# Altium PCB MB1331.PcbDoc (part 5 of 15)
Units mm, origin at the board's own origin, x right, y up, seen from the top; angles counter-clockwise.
Board outline 169.25 x 173.25 mm, 6 copper layers (Top Layer, Signal Layer 1, Signal Layer 2, Signal Layer 3, Signal Layer 4, Bottom Layer), stack 1.556 mm thick; 871 components, 699 nets, 3244 pads, 2370 vias.
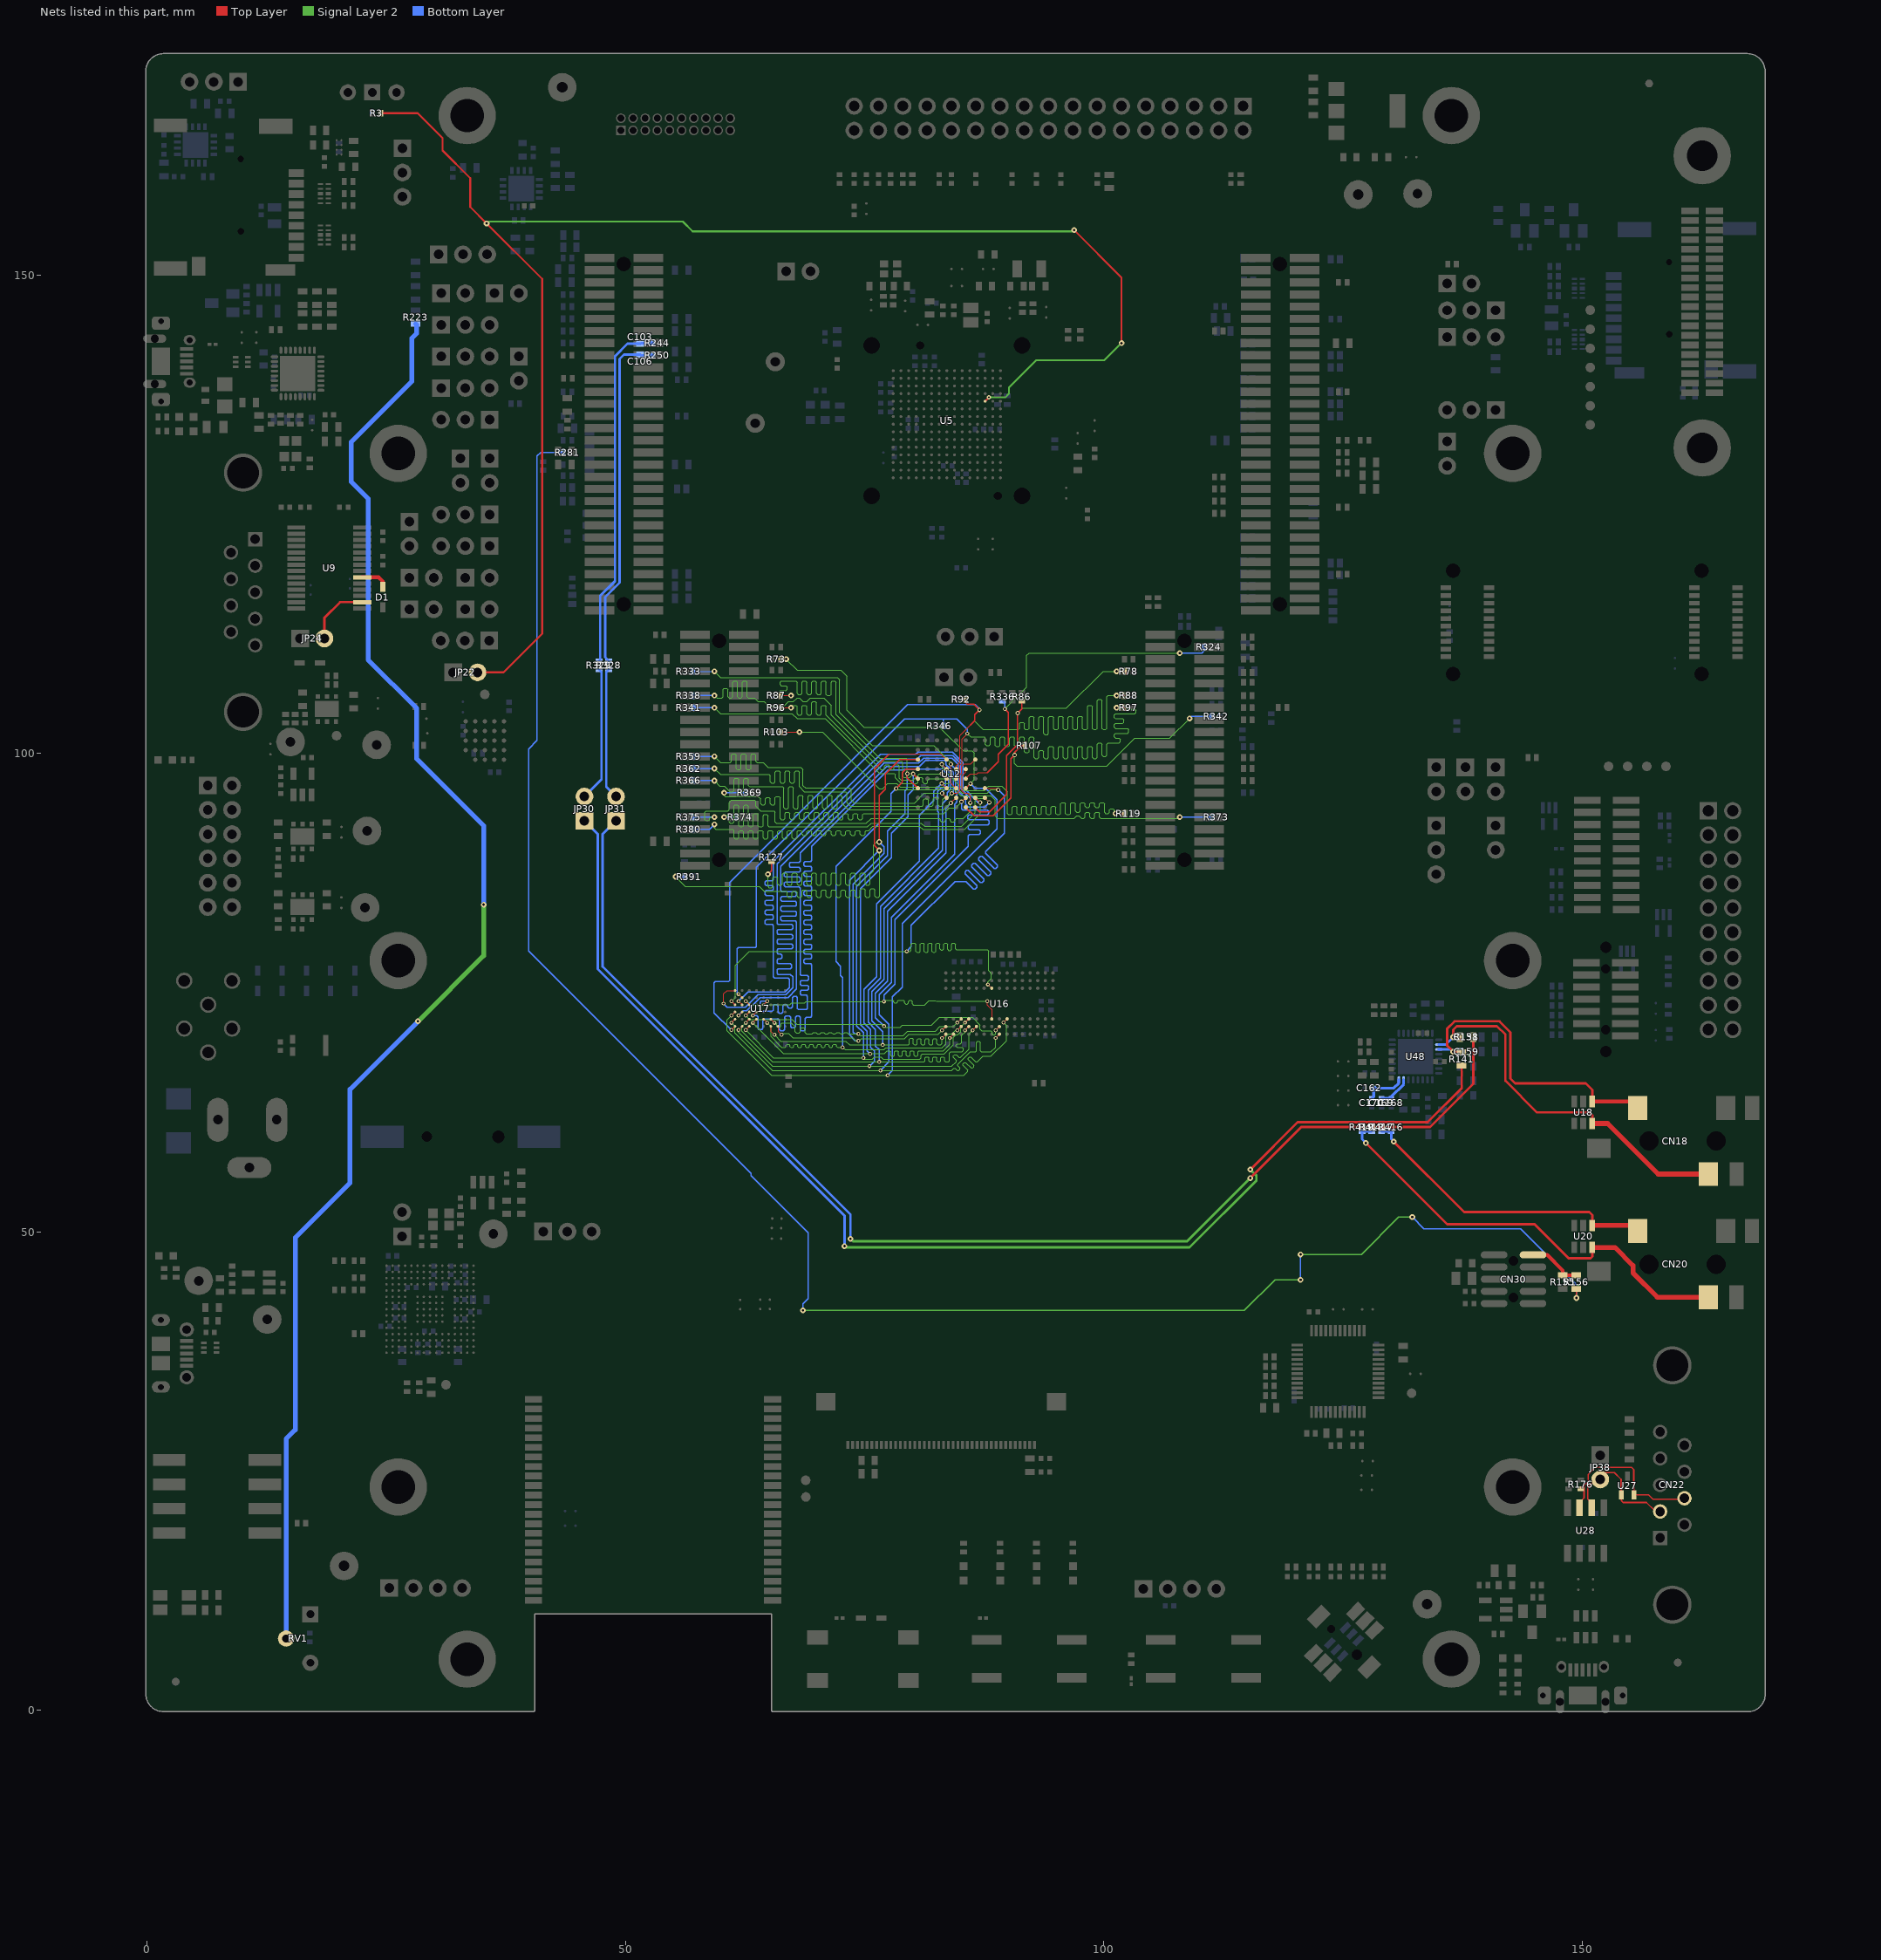
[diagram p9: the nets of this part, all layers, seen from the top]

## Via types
v1: diameter 0.6, hole 0.254, Top Layer to Bottom Layer, tented both sides, 1747 vias
v2: diameter 0.45, hole 0.2, Top Layer to Bottom Layer, tented both sides, 272 vias
v3: diameter 0.406, hole 0.203, Top Layer to Bottom Layer, tented both sides, 160 vias
v4: diameter 0.6, hole 0.25, Top Layer to Bottom Layer, tented both sides, 82 vias
v5: diameter 0.45, hole 0.25, Top Layer to Bottom Layer, tented both sides, 45 vias
v6: diameter 0.5, hole 0.25, Top Layer to Bottom Layer, tented both sides, 23 vias
v7: diameter 1.016, hole 0.508, Top Layer to Bottom Layer, tented both sides, 17 vias
v8: diameter 0.508, hole 0.254, Top Layer to Bottom Layer, tented both sides, 9 vias
v9: diameter 0.61, hole 0.305, Top Layer to Bottom Layer, tented both sides, 7 vias
v10: diameter 0.5, hole 0.254, Top Layer to Bottom Layer, tented both sides, 6 vias
v11: diameter 0.4, hole 0.2, Top Layer to Bottom Layer, tented both sides, 1 vias
v12: diameter 0.483, hole 0.254, Top Layer to Bottom Layer, tented both sides, 1 vias

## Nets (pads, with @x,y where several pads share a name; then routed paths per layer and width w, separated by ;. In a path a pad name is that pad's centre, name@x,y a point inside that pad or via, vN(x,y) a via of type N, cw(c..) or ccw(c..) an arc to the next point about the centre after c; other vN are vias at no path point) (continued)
A9: R103.2 U12.A6 U16.J3 U17.H3 | length 108.3
  Top Layer w0.102: v3(61.078,74.105) U17.H3@61.453,73.73 ; R103.2@66.236,102.235 v1(68.199,102.235) ; U12.A6@87.574,96.366 88.806,96.366 v5(88.97,96.203) ; v3(87.896,75.863) U16.J3@88.297,75.463
  Signal Layer 2 w0.102: v3(61.078,74.105) 61.472,74.5 61.472,77.862 62.935,79.324 v3(79.406,79.324) 79.749,79.324 79.876,79.451 79.876,80.061 80.003,80.188 80.232,80.188 80.359,80.061 80.359,79.324 80.486,79.197 80.71,79.197 80.837,79.324 80.837,80.069 80.956,80.188 81.124,80.188 81.243,80.069 81.243,79.316 81.362,79.197 81.53,79.197 81.65,79.316 81.65,80.069 81.769,80.188 81.937,80.188 82.056,80.069 82.056,79.316 82.175,79.197 82.343,79.197 82.462,79.316 82.462,80.069 82.581,80.188 82.75,80.188 82.869,80.069 82.869,79.57 82.988,79.451 83.156,79.451 83.275,79.57 83.275,80.069 83.394,80.188 83.562,80.188 83.682,80.069 83.682,79.52 83.801,79.401 83.969,79.401 84.088,79.52 84.088,80.061 84.19,80.163 84.393,80.163 84.494,80.061 84.494,79.604 84.596,79.502 87.827,79.502 87.954,79.375 87.954,77.292 88.258,76.988 88.258,76.48 87.896,76.118 v3(87.896,75.863) ; v1(68.199,102.235) 70.612,102.235 76.53,96.317 76.886,96.317 77.419,96.85 78.357,96.85 78.735,96.472 84.566,96.472 85.204,95.834 87.833,95.834 88.202,96.202 v5(88.97,96.203)
  Bottom Layer w0.127: v3(79.406,79.324) 79.876,79.801 79.876,82.037 84.454,86.614 85.58,86.614 86.385,85.809 86.564,85.809 86.745,85.989 86.745,86.169 85.489,87.425 85.489,87.604 85.669,87.784 85.848,87.784 87.104,86.528 87.283,86.528 87.463,86.708 87.463,86.887 86.195,88.156 86.195,88.335 86.375,88.516 86.555,88.516 87.823,87.247 88.002,87.247 88.182,87.427 88.182,87.606 86.914,88.875 86.914,89.054 87.094,89.234 87.273,89.234 88.542,87.966 88.721,87.966 88.905,88.15 88.905,88.33 87.675,89.559 87.675,89.739 89.605,91.669 89.605,95.568 v5(88.97,96.203)
A10: R73.1 U12.C6 U16.G7 U17.H4 | length 108.3
  Top Layer w0.102: v3(61.078,72.605) U17.H4@61.453,72.98 ; R73.1@66.236,109.855 v1(66.802,109.855) ; U12.C6@85.574,96.366 85.583,96.366 v5(86.067,96.85) ; v3(89.52,71.886) U16.G7@89.897,72.263
  Signal Layer 2 w0.102: v3(61.078,72.605) 60.649,72.176 60.649,70.993 65.271,66.37 v3(77.413,66.37) 85.374,66.37 85.795,66.791 85.795,66.891 85.263,67.422 85.263,67.566 85.407,67.71 85.551,67.71 86.131,67.129 86.299,67.129 86.419,67.249 86.419,67.417 85.838,67.997 85.838,68.141 85.982,68.285 86.126,68.285 86.618,67.793 86.785,67.793 87.357,68.364 88.22,68.364 89.833,69.977 89.833,71.572 v3(89.52,71.886) ; v1(66.802,109.855) 67.945,108.712 72.517,108.712 73.152,108.077 73.152,104.521 74.931,102.742 82.831,102.742 83.325,102.248 83.325,102.242 85.307,100.26 86.237,100.26 86.468,100.029 86.468,97.251 v5(86.067,96.85)
  Bottom Layer w0.127: v3(77.413,66.37) 77.921,66.878 77.921,74.565 78.949,75.594 78.949,82.233 88.843,92.126 88.843,95.149 87.649,96.342 86.575,96.342 v5(86.067,96.85)
A11: R333.1 U12.D6 U16.H9 U17.H5 | length 108.2
  Top Layer w0.102: v3(61.078,71.855) U17.H5@61.453,72.23 ; v5(84.017,98.882) 84.017,96.917 U12.D6@84.574,96.366 ; v3(88.697,70.263) U16.H9@89.097,70.663
  Signal Layer 2 w0.102: v1(59.309,108.585) 59.944,107.95 72.136,107.95 72.39,107.696 72.39,104.267 75.819,100.838 82.245,100.838 84.023,99.06 v5(84.017,98.882) ; v3(61.078,71.855) 61.433,71.5 61.433,70.793 65.348,66.878 v3(76.651,66.878) 84.118,66.878 84.315,67.075 84.459,67.075 84.684,66.851 84.827,66.851 84.971,66.995 84.971,67.138 84.747,67.363 84.747,67.507 86.061,68.821 86.582,68.821 86.684,68.923 86.684,69.807 86.803,69.926 86.971,69.926 87.09,69.807 87.09,68.923 87.192,68.821 88.22,68.821 88.697,69.298 v3(88.697,70.263)
  Bottom Layer w0.102: R333.1@57.088,108.585 v1(59.309,108.585)
  Bottom Layer w0.127: v3(76.651,66.878) 77.54,67.767 77.54,71.677 76.524,72.693 76.524,74.785 77.794,76.055 77.794,82.88 84.398,89.484 84.398,94.674 84.652,94.928 84.652,95.834 84.525,95.961 84.525,98.374 v5(84.017,98.882)
A12: R380.1 U12.B7 U17.G3 | length 107.6
  Top Layer w0.102: v3(61.828,74.105) U17.G3@62.203,73.73 ; v5(87.067,94.866) U12.B7@86.602,95.331 ; U12.B7@86.602,95.331 86.599,95.335 U12.B7@86.574,95.366 U12.B7@86.602,95.331
  Signal Layer 2 w0.1: 59.944,92.075 61.214,92.075 61.341,91.948 61.341,91.186 61.468,91.059 61.722,91.059 61.849,91.186 61.849,91.821 61.976,91.948 62.23,91.948 62.357,91.821 62.357,91.186 62.484,91.059 62.738,91.059 62.865,91.186 62.865,91.821 62.992,91.948 63.246,91.948 63.373,91.821 63.373,91.186 63.5,91.059 63.754,91.059 63.881,91.186 63.881,91.821 64.008,91.948 64.262,91.948 64.389,91.821 64.389,91.186 64.516,91.059 64.77,91.059 64.897,91.186 64.897,91.821 65.024,91.948 65.278,91.948 65.405,91.821 65.405,91.186 65.532,91.059 65.786,91.059 65.913,91.186 65.913,91.821 66.04,91.948 66.294,91.948 66.421,91.821 66.421,91.186 66.548,91.059 66.802,91.059 66.929,91.186 66.929,91.821 67.056,91.948 67.31,91.948 67.437,91.821 67.437,91.186 67.564,91.059 67.818,91.059 67.945,91.186 67.945,91.821 68.072,91.948 68.326,91.948 68.453,91.821 68.453,91.567 68.58,91.44 68.834,91.44 68.961,91.567 68.961,91.821 69.088,91.948 69.342,91.948 69.469,91.821 69.469,91.567 69.596,91.44 69.85,91.44 69.977,91.567 69.977,91.821 70.104,91.948 70.358,91.948 70.485,91.821 70.485,91.567 70.612,91.44 70.866,91.44 70.993,91.567 70.993,91.821 71.12,91.948 71.374,91.948 71.501,91.821 71.501,91.567 71.628,91.44 71.882,91.44 72.009,91.567 72.009,91.821 72.136,91.948 72.39,91.948 72.517,91.821 72.517,91.567 72.644,91.44 72.898,91.44 73.025,91.567 73.025,91.821 73.152,91.948 73.406,91.948 73.533,91.821 73.533,91.567 73.66,91.44 73.914,91.44 74.041,91.567 74.041,91.821 74.168,91.948 74.422,91.948 74.549,91.821 74.549,91.567 74.676,91.44 74.93,91.44 75.057,91.567 75.057,91.821 75.184,91.948 75.438,91.948
  Signal Layer 2 w0.102: v1(59.309,92.583) 59.309,92.202 59.436,92.075 59.944,92.075 ; 75.438,91.948 75.87,92.38 80.747,92.38 81.077,92.049 85.446,92.049 87.071,93.675 v5(87.067,94.866)
  Bottom Layer w0.127: R380.1@57.088,92.075 58.801,92.075 v1(59.309,92.583) ; v3(61.828,74.105) 62.805,75.083 66.694,75.083 67.126,75.514 67.126,76.403 66.999,76.53 65.602,76.53 65.475,76.657 65.475,81.989 65.348,82.116 64.713,82.116 64.586,82.243 64.586,82.497 64.713,82.624 65.348,82.624 65.475,82.751 65.475,83.005 65.348,83.132 64.713,83.132 64.586,83.259 64.586,83.513 64.713,83.64 65.348,83.64 65.475,83.767 65.475,84.021 65.348,84.148 64.713,84.148 64.586,84.275 64.586,84.529 64.713,84.656 65.348,84.656 65.475,84.783 65.475,85.037 65.348,85.164 64.713,85.164 64.586,85.291 64.586,85.545 64.713,85.672 65.348,85.672 65.475,85.799 65.475,86.053 65.348,86.18 64.713,86.18 64.586,86.307 64.586,86.561 64.713,86.688 65.348,86.688 65.475,86.815 65.475,88.722 76.651,99.898 80.334,99.898 80.588,100.152 84.177,100.152 85.287,99.043 85.287,96.469 86.89,94.866 v5(87.067,94.866)
A13: R374.1 U12.A7 U17.G4 | length 107.6
  Top Layer w0.102: v3(61.828,72.605) U17.G4@62.203,72.98 ; U12.A7@87.574,95.366 v5(88.042,94.891)
  Signal Layer 2 w0.102: v1(60.325,93.345) 60.515,93.535 60.706,93.535 60.833,93.408 60.833,92.837 60.96,92.71 61.214,92.71 61.341,92.837 61.341,94.488 61.468,94.615 61.722,94.615 61.849,94.488 61.849,92.456 61.976,92.329 62.23,92.329 62.357,92.456 62.357,94.488 62.484,94.615 62.738,94.615 62.865,94.488 62.865,92.456 62.992,92.329 63.246,92.329 63.373,92.456 63.373,93.599 63.5,93.726 63.754,93.726 63.881,93.599 63.881,92.456 64.008,92.329 64.262,92.329 64.389,92.456 64.389,93.472 64.516,93.599 64.77,93.599 64.897,93.472 64.897,92.456 65.024,92.329 75.311,92.329 75.692,92.71 80.925,92.71 81.255,92.38 85.141,92.38 86.563,93.802 86.563,95.021 86.868,95.326 87.614,95.326 v5(88.042,94.891)
  Bottom Layer w0.102: v1(60.325,93.345) R374.1@61.526,93.345
  Bottom Layer w0.127: v3(61.828,72.605) 62.323,73.101 62.681,73.101 64.078,74.498 66.999,74.498 67.888,75.387 67.888,82.382 67.761,82.509 66.364,82.509 66.237,82.636 66.237,82.89 66.364,83.017 67.761,83.017 67.888,83.144 67.888,83.398 67.761,83.525 66.364,83.525 66.237,83.652 66.237,83.906 66.364,84.033 67.761,84.033 67.888,84.16 67.888,84.414 67.761,84.541 66.364,84.541 66.237,84.668 66.237,84.922 66.364,85.049 67.761,85.049 67.888,85.176 67.888,85.43 67.761,85.557 66.364,85.557 66.237,85.684 66.237,88.214 77.032,99.009 80.651,99.009 81.159,99.517 84.144,99.517 84.779,98.882 84.779,96.088 85.541,95.326 85.541,94.691 85.82,94.412 87.562,94.412 v5(88.042,94.891)
A14: R369.1 U12.C7 U16.J7 U17.F3 | length 108.2
  Top Layer w0.102: v3(62.578,74.105) U17.F3@62.953,73.73 ; v5(85.134,94.945) 85.147,94.945 U12.C7@85.574,95.366 ; v3(87.827,74.117) 87.827,73.711 88.296,73.241 U16.J7@88.297,72.263
  Signal Layer 2 w0.102: v1(60.325,95.885) 60.325,95.631 60.452,95.504 63.881,95.504 64.135,95.25 64.135,94.742 64.262,94.615 64.516,94.615 64.643,94.742 64.643,95.25 64.77,95.377 65.024,95.377 65.151,95.25 65.151,94.742 65.278,94.615 65.532,94.615 65.659,94.742 65.659,95.377 65.786,95.504 66.04,95.504 66.167,95.377 66.167,93.218 66.294,93.091 66.548,93.091 66.675,93.218 66.675,93.726 66.802,93.853 67.056,93.853 67.183,93.726 67.183,93.218 67.31,93.091 67.564,93.091 67.691,93.218 67.691,93.726 67.818,93.853 68.072,93.853 68.199,93.726 68.199,93.218 68.326,93.091 68.58,93.091 68.707,93.218 68.707,93.726 68.834,93.853 69.088,93.853 69.215,93.726 69.215,93.218 69.342,93.091 69.596,93.091 69.723,93.218 69.723,93.726 69.85,93.853 70.104,93.853 70.231,93.726 70.231,93.218 70.358,93.091 70.612,93.091 70.739,93.218 70.739,93.726 70.866,93.853 71.12,93.853 71.247,93.726 71.247,93.218 71.374,93.091 71.628,93.091 71.755,93.218 71.755,93.726 71.882,93.853 72.136,93.853 72.263,93.726 72.263,93.218 72.39,93.091 72.644,93.091 72.771,93.218 72.771,93.599 72.898,93.726 73.152,93.726 73.279,93.599 73.279,93.218 73.406,93.091 73.66,93.091 73.787,93.218 73.787,93.599 73.914,93.726 74.168,93.726 74.295,93.599 74.295,93.218 74.422,93.091 74.676,93.091 74.803,93.218 74.803,93.599 74.93,93.726 83.287,93.726 83.871,94.31 84.506,94.31 v5(85.134,94.945) ; v3(62.578,74.105) 62.693,74.105 63.062,73.736 67.188,73.736 67.391,73.94 68.736,73.94 68.878,74.081 v3(77.017,74.081) 77.129,74.194 77.933,74.194 78.034,74.092 78.034,74.041 78.136,73.94 78.339,73.94 78.441,74.041 78.441,74.092 78.542,74.194 79.064,74.194 79.191,74.067 79.191,73.94 79.318,73.813 79.47,73.813 79.597,73.94 79.597,74.082 79.708,74.194 79.866,74.194 79.978,74.082 79.978,73.838 80.105,73.711 81.276,73.711 81.733,74.168 82.431,74.168 82.482,74.117 v3(87.827,74.117)
  Bottom Layer w0.127: v1(60.325,95.885) R369.1@62.542,95.885 ; v3(77.017,74.081) 77.017,74.739 78.175,75.897 78.175,82.626 85.833,90.284 85.833,91.389 85.96,91.516 86.988,91.516 87.115,91.643 87.115,91.897 86.988,92.024 85.96,92.024 85.833,92.151 85.833,92.405 85.96,92.532 87.877,92.532 88.004,92.659 88.004,92.939 87.877,93.066 85.896,93.066 85.769,93.193 85.769,93.447 85.896,93.574 87.827,93.574 87.954,93.701 87.954,93.955 87.827,94.082 85.261,94.082 85.134,94.209 v5(85.134,94.945)
A15: R366.1 U12.D7 U16.H8 U17.F4 | length 108.3
  Top Layer w0.102: v3(62.578,72.605) U17.F4@62.953,72.98 ; v5(84.017,94.831) U12.D7@84.574,95.366 ; v3(88.697,71.063) U16.H8@89.097,71.463
  Signal Layer 2 w0.102: v1(59.309,97.155) 59.868,96.596 60.376,96.596 60.96,96.012 61.214,96.012 61.341,96.139 61.341,97.282 61.468,97.409 61.722,97.409 61.849,97.282 61.849,96.139 61.976,96.012 62.23,96.012 62.357,96.139 62.357,97.282 62.484,97.409 62.738,97.409 62.865,97.282 62.865,96.647 62.992,96.52 66.421,96.52 66.548,96.393 66.548,94.361 66.675,94.234 66.929,94.234 67.056,94.361 67.056,96.393 67.183,96.52 67.437,96.52 67.564,96.393 67.564,94.361 67.691,94.234 67.945,94.234 68.072,94.361 68.072,95.504 68.199,95.631 68.453,95.631 68.58,95.504 68.58,94.361 68.707,94.234 68.961,94.234 69.088,94.361 69.088,95.504 69.215,95.631 69.469,95.631 69.596,95.504 69.596,94.361 69.723,94.234 69.977,94.234 70.104,94.361 70.104,95.504 70.231,95.631 70.485,95.631 70.612,95.504 70.612,94.361 70.739,94.234 70.993,94.234 71.12,94.361 71.12,95.504 71.247,95.631 71.501,95.631 71.628,95.504 71.628,94.361 71.755,94.234 72.009,94.234 72.136,94.361 72.136,95.504 72.263,95.631 72.517,95.631 72.644,95.504 72.644,94.742 73.279,94.107 83.3,94.107 84.02,94.828 v5(84.017,94.831) ; v3(62.578,72.605) 62.971,72.212 65.73,72.211 67.406,72.211 67.913,71.704 76.778,71.704 76.981,71.501 v3(77.032,71.501) 77.159,71.374 78.733,71.374 78.962,71.603 81.985,71.603 82.804,72.422 86.271,72.422 87.065,71.628 87.065,71.196 87.242,71.019 88.208,71.019 88.335,70.892 88.335,70.718 88.441,70.612 88.591,70.612 88.697,70.718 v3(88.697,71.063)
  Bottom Layer w0.127: R366.1@57.088,97.155 v1(59.309,97.155) ; v3(77.032,71.501) 76.143,72.39 76.143,74.943 77.413,76.213 77.413,83.515 83.509,89.611 83.509,94.31 84.017,94.818 v5(84.017,94.831)
A16: R359.2 U12.E7 U17.E4 | length 107.4
  Top Layer w0.102: v3(63.328,72.605) U17.E4@63.703,72.98 ; v5(83.102,95.834) 83.567,95.366 U12.E7@83.574,95.366
  Signal Layer 2 w0.102: v1(59.309,99.695) 59.944,99.06 60.96,99.06 61.087,99.187 61.087,99.822 61.214,99.949 61.468,99.949 61.595,99.822 61.595,98.425 61.722,98.298 61.976,98.298 62.103,98.425 62.103,99.822 62.23,99.949 62.484,99.949 62.611,99.822 62.611,98.425 62.738,98.298 62.992,98.298 63.119,98.425 63.119,99.822 63.246,99.949 63.5,99.949 63.627,99.822 63.627,99.187 63.754,99.06 64.389,99.06 64.897,98.552 68.326,98.552 68.58,98.298 68.58,96.647 68.834,96.393 73.406,96.393 73.609,96.19 73.609,95.123 73.914,94.818 80.223,94.818 81.239,95.834 v5(83.102,95.834)
  Bottom Layer w0.127: R359.2@57.088,99.695 v1(59.309,99.695) ; v3(63.328,72.605) 63.71,72.605 63.849,72.466 63.849,71.298 63.976,71.171 64.255,71.171 64.382,71.298 64.382,72.097 64.509,72.224 65.957,72.224 66.084,72.097 66.084,71.146 66.211,71.019 66.516,71.019 66.643,71.146 66.643,72.441 66.77,72.568 67.141,72.568 67.268,72.441 67.268,71.476 67.395,71.349 67.649,71.349 67.776,71.476 67.776,72.441 67.903,72.568 68.157,72.568 68.284,72.441 68.284,71.12 68.411,70.993 68.665,70.993 68.792,71.12 68.792,72.314 68.919,72.441 69.361,72.441 69.488,72.568 69.488,77.898 69.361,78.025 68.777,78.025 68.65,78.152 68.65,78.406 68.777,78.533 69.361,78.533 69.488,78.66 69.488,78.914 69.361,79.041 68.777,79.041 68.65,79.168 68.65,79.422 68.777,79.549 69.361,79.549 69.488,79.676 69.488,79.93 69.361,80.057 68.777,80.057 68.65,80.184 68.65,80.438 68.777,80.565 69.361,80.565 69.488,80.692 69.488,80.946 69.361,81.073 68.777,81.073 68.65,81.2 68.65,81.454 68.777,81.581 69.361,81.581 69.488,81.708 69.488,81.962 69.361,82.089 68.777,82.089 68.65,82.216 68.65,82.47 68.777,82.597 69.361,82.597 69.488,82.724 69.488,82.978 69.361,83.105 68.777,83.105 68.65,83.232 68.65,83.486 68.777,83.613 69.361,83.613 69.488,83.74 69.488,83.994 69.361,84.121 68.777,84.121 68.65,84.248 68.65,84.502 68.777,84.629 69.361,84.629 69.488,84.756 69.488,85.01 69.361,85.137 68.777,85.137 68.65,85.264 68.65,85.518 68.777,85.645 69.361,85.645 69.488,85.772 69.488,86.026 69.361,86.153 68.777,86.153 68.65,86.28 68.65,86.534 68.777,86.661 69.361,86.661 69.488,86.788 69.488,87.042 69.361,87.169 68.777,87.169 68.65,87.296 68.65,87.55 68.777,87.677 69.361,87.677 69.488,87.804 69.488,88.058 69.361,88.185 68.777,88.185 68.65,88.312 68.65,88.566 68.777,88.693 69.361,88.693 69.488,88.82 69.488,90.292 77.444,98.247 79.064,98.247 79.191,98.374 83.134,98.374 83.474,98.028 83.763,97.739 83.763,96.596 83.102,95.936 v5(83.102,95.834)
A17: R362.2 U12.B3 U17.D3 | length 108.1
  Top Layer w0.102: U17.D3@64.453,73.73 v3(64.827,74.105) ; v5(84.118,95.834) 84.677,95.834 84.967,96.124 84.967,97.75 85.168,97.951 85.168,98.654 85.421,98.908 86.109,98.908 U12.B3@86.574,99.366
  Signal Layer 2 w0.102: v1(59.309,98.425) 59.944,97.79 65.024,97.79 65.151,97.663 65.151,97.028 65.278,96.901 65.532,96.901 65.659,97.028 65.659,98.044 65.786,98.171 66.04,98.171 66.167,98.044 66.167,97.028 66.294,96.901 66.548,96.901 66.675,97.028 66.675,98.044 66.802,98.171 67.056,98.171 67.183,98.044 67.183,97.028 67.31,96.901 67.564,96.901 67.691,97.028 67.691,98.044 67.818,98.171 68.072,98.171 68.199,98.044 68.199,96.52 68.707,96.012 73.025,96.012 73.152,95.885 73.152,94.869 73.533,94.488 81.026,94.488 81.153,94.615 81.153,95.123 81.28,95.25 81.534,95.25 81.661,95.123 81.661,94.615 81.788,94.488 82.042,94.488 82.169,94.615 82.169,95.25 82.296,95.377 82.55,95.377 82.677,95.25 82.677,94.615 82.804,94.488 83.058,94.488 83.185,94.615 83.185,95.236 83.312,95.363 83.649,95.363 v5(84.118,95.834)
  Bottom Layer w0.127: R362.2@57.088,98.425 v1(59.309,98.425) ; v3(64.827,74.105) 64.205,74.105 64.078,73.978 64.078,73.178 64.205,73.051 65.314,73.051 65.441,73.178 65.441,73.609 65.568,73.736 65.822,73.736 65.949,73.609 65.949,72.974 66.076,72.847 66.33,72.847 66.457,72.974 66.457,73.609 66.584,73.736 66.838,73.736 66.965,73.609 66.965,73.508 67.092,73.381 67.346,73.381 67.473,73.508 67.473,74.498 67.6,74.625 67.854,74.625 67.981,74.498 67.981,73.355 68.108,73.228 68.904,73.228 69.031,73.355 69.031,74.625 68.904,74.752 68.396,74.752 68.269,74.879 68.269,75.133 68.396,75.26 69.031,75.26 69.158,75.387 69.158,75.641 69.031,75.768 68.396,75.768 68.269,75.895 68.269,76.149 68.396,76.276 69.031,76.276 69.158,76.403 69.158,76.657 69.031,76.784 68.396,76.784 68.269,76.911 68.269,85.938 68.142,86.065 66.745,86.065 66.618,86.192 66.618,86.446 66.745,86.573 68.142,86.573 68.269,86.7 68.269,86.954 68.142,87.081 66.745,87.081 66.618,87.208 66.618,87.462 66.745,87.589 68.142,87.589 68.269,87.716 68.269,87.97 68.142,88.097 67.253,88.097 67.126,88.224 67.126,88.478 67.253,88.605 68.142,88.605 68.269,88.732 68.269,89.611 77.286,98.628 80.715,98.628 81.359,99.273 83.372,99.273 83.509,99.136 83.509,98.815 83.848,98.476 83.857,98.476 84.271,98.063 84.271,95.987 v5(84.118,95.834)
A18: R375.2 U12.C4 U17.H1 | length 107.7
  Top Layer w0.102: v3(60.268,73.863) 60.268,74.867 60.631,75.23 U17.H1@61.453,75.23 ; U12.C4@85.574,98.366 85.568,98.02 85.171,97.623 85.171,96.077 85.414,95.834 85.795,95.834 86.049,95.58 v5(86.049,94.844)
  Signal Layer 2 w0.102: v1(59.309,93.345) 58.928,93.345 58.801,93.218 58.801,93.091 58.674,92.964 58.42,92.964 58.293,93.091 58.293,93.853 58.42,93.98 60.706,93.98 60.833,94.107 60.833,94.869 61.087,95.123 63.5,95.123 63.627,94.996 63.627,94.488 64.135,93.98 65.532,93.98 65.659,93.853 65.659,92.837 65.786,92.71 75.184,92.71 75.692,93.218 82.804,93.218 82.931,93.091 82.931,92.964 83.058,92.837 83.312,92.837 83.439,92.964 83.439,93.091 83.566,93.218 83.82,93.218 83.947,93.091 83.947,92.964 84.074,92.837 84.328,92.837 84.455,92.964 84.455,93.091 84.582,93.218 85.344,93.218 86.049,93.923 v5(86.049,94.844)
  Bottom Layer w0.127: R375.2@57.088,93.345 v1(59.309,93.345) ; v3(60.268,73.863) 60.649,73.482 62.554,73.482 63.874,74.803 66.795,74.803 67.507,75.514 67.507,76.657 67.253,76.911 65.983,76.911 65.856,77.038 65.856,77.381 65.983,77.508 67.253,77.508 67.38,77.635 67.38,77.889 67.253,78.016 65.983,78.016 65.856,78.143 65.856,78.397 65.983,78.524 66.237,78.524 66.364,78.651 66.364,78.905 66.237,79.032 65.983,79.032 65.856,79.159 65.856,79.449 65.983,79.576 67.38,79.576 67.507,79.703 67.507,79.957 67.38,80.084 65.983,80.084 65.856,80.211 65.856,80.465 65.983,80.592 67.38,80.592 67.507,80.719 67.507,80.973 67.38,81.1 65.983,81.1 65.856,81.227 65.856,81.481 65.983,81.608 67.38,81.608 67.507,81.735 67.507,81.989 67.38,82.116 65.983,82.116 65.856,82.243 65.856,88.468 76.816,99.428 80.499,99.428 80.858,99.788 84.218,99.788 85.033,98.973 85.033,96.342 86.049,95.326 v5(86.049,94.844)
A19: R97.2 R346.2 U12.D5 U17.G2 | length 109
  Top Layer w0.102: v3(61.828,74.855) U17.G2@62.203,74.48 ; U12.D5@84.574,97.366 84.568,97.655 84.964,98.052 84.964,98.777 85.171,98.983 85.171,101.509 v3(85.735,102.073) ; v1(101.346,104.775) R97.2@102.166,104.775
  Signal Layer 2 w0.102: v3(85.735,102.073) 86.089,101.727 87.502,101.727 87.629,101.6 87.63,101.092 87.63,100.965 87.757,100.838 88.011,100.838 88.138,100.965 88.138,101.6 88.265,101.727 88.519,101.727 88.646,101.6 88.646,100.838 88.773,100.711 89.027,100.711 89.154,100.838 89.154,101.6 89.281,101.727 89.535,101.727 89.662,101.6 89.662,100.838 89.789,100.711 90.043,100.711 90.17,100.838 90.17,101.6 90.297,101.727 90.551,101.727 90.678,101.6 90.678,100.838 90.805,100.711 91.059,100.711 91.186,100.838 91.186,101.6 91.313,101.727 91.567,101.727 91.694,101.6 91.694,100.203 91.821,100.076 92.075,100.076 92.202,100.203 92.202,101.6 92.329,101.727 92.583,101.727 92.71,101.6 92.71,99.568 92.837,99.441 93.091,99.441 93.218,99.568 93.218,100.203 93.345,100.33 93.599,100.33 93.726,100.203 93.726,99.568 93.853,99.441 94.107,99.441 94.234,99.568 94.234,100.584 94.361,100.711 94.615,100.711 94.742,100.584 94.742,99.568 94.869,99.441 95.123,99.441 95.25,99.568 95.25,100.584 95.377,100.711 95.631,100.711 95.758,100.584 95.758,99.568 95.885,99.441 96.139,99.441 96.266,99.568 96.266,100.584 96.393,100.711 96.647,100.711 96.774,100.584 96.774,99.568 96.901,99.441 97.155,99.441 97.282,99.568 97.282,100.584 97.409,100.711 97.663,100.711 97.79,100.584 97.79,99.568 97.917,99.441 98.171,99.441 98.298,99.568 98.298,100.584 98.425,100.711 98.679,100.711 98.806,100.584 98.806,99.568 98.933,99.441 99.187,99.441 99.314,99.568 99.314,100.965 99.441,101.092 99.695,101.092 99.822,100.965 99.822,99.822 99.949,99.695 100.203,99.695 100.33,99.822 100.33,100.965 100.457,101.092 101.6,101.092 101.727,101.219 101.727,101.473 101.6,101.6 101.219,101.6 101.092,101.727 101.092,101.981 101.219,102.108 102.489,102.108 102.616,102.235 102.616,102.489 102.489,102.616 101.219,102.616 101.092,102.743 101.092,102.997 101.219,103.124 101.981,103.124 102.108,103.251 102.108,103.505 101.981,103.632 101.219,103.632 101.092,103.759 101.092,104.013 101.219,104.14 103.251,104.14 103.378,104.267 103.378,104.521 103.251,104.648 101.473,104.648 v1(101.346,104.775)
  Bottom Layer w0.127: v3(61.828,74.855) 61.69,74.993 61.69,79.578 61.817,79.705 63.57,79.705 63.697,79.832 63.697,88.087 79.191,103.581 83.254,103.581 ; R346.2@83.254,102.87 83.254,103.523 83.254,103.581 ; v3(85.735,102.073) 85.735,102.497 84.651,103.581 83.254,103.581
A20: R88.2 R92.2 U12.D4 U17.H6 | length 110.4
  Top Layer w0.102: v3(61.078,71.105) U17.H6@61.453,71.48 ; U12.D4@84.574,98.366 84.568,98.694 84.968,99.094 84.968,101.865 86.049,102.946 ; v1(101.346,106.045) R88.2@102.166,106.045
  Top Layer w0.127: R92.2@85.54,105.664 85.54,105.341 85.725,105.156 86.404,105.156 v5(87.014,104.547) 86.531,104.064 86.531,103.429 86.049,102.946
  Signal Layer 2 w0.102: v5(87.014,104.547) 86.513,104.038 86.513,103.378 87.401,102.489 91.059,102.489 91.186,102.616 91.186,103.124 91.313,103.251 91.567,103.251 91.694,103.124 91.694,102.616 91.821,102.489 92.075,102.489 92.202,102.616 92.202,103.759 92.329,103.886 92.583,103.886 92.71,103.759 92.71,102.616 92.837,102.489 93.091,102.489 93.218,102.616 93.218,103.759 93.345,103.886 93.599,103.886 93.726,103.759 93.726,102.108 93.853,101.981 94.107,101.981 94.234,102.108 94.234,103.759 94.361,103.886 94.615,103.886 94.742,103.759 94.742,102.616 94.869,102.489 95.123,102.489 95.25,102.616 95.25,103.759 95.377,103.886 95.631,103.886 95.758,103.759 95.758,102.616 95.885,102.489 96.139,102.489 96.266,102.616 96.266,103.759 96.393,103.886 96.647,103.886 96.774,103.759 96.774,102.616 96.901,102.489 97.155,102.489 97.282,102.616 97.282,103.759 97.409,103.886 97.663,103.886 97.79,103.759 97.79,102.616 97.917,102.489 98.171,102.489 98.298,102.616 98.298,104.902 98.425,105.029 98.679,105.029 98.806,104.902 98.806,102.616 98.933,102.489 99.187,102.489 99.314,102.616 99.314,105.537 99.441,105.664 99.695,105.664 99.822,105.537 99.822,102.616 99.949,102.489 100.203,102.489 100.33,102.616 100.33,105.918 100.457,106.045 v1(101.346,106.045)
  Bottom Layer w0.127: v3(61.078,71.105) 59.277,72.906 59.277,76.022 59.404,76.149 60.776,76.149 60.903,76.276 60.903,86.523 79.485,105.105 86.557,105.105 87.014,104.648 v5(87.014,104.547)
A21: R324.2 R336.2 U12.C5 | length 36.9
  Top Layer w0.102: U12.C5@85.574,97.366 86.068,97.866 86.762,97.866 86.876,97.981 87.814,97.981
  Top Layer w0.127: 87.814,97.981 88.97,99.136 88.97,99.892 90.043,100.965 90.043,104.267 v5(89.662,104.648)
  Signal Layer 2 w0.102: v5(89.662,104.648) 91.948,106.934 91.948,110.236 92.202,110.49 v1(107.95,110.49)
  Bottom Layer w0.127: R336.2@89.408,105.468 89.662,105.214 v5(89.662,104.648) ; v1(107.95,110.49) 110.236,110.49 110.532,110.786 R324.2@110.532,111.125
A22: R78.2 R86.2 U12.B8 | length 27.6
  Top Layer w0.102: v1(101.346,108.585) R78.2@102.166,108.585
  Top Layer w0.127: U12.B8@86.574,94.366 87.03,93.904 88.055,93.904 89.859,95.707 89.859,99.765 90.992,100.898 v5(90.992,104.207) 91.44,104.655 R86.2@91.44,105.468
  Signal Layer 2 w0.102: v5(90.992,104.207) 91.516,104.724 96.088,104.724 99.949,108.585 v1(101.346,108.585)
A23: R107.2 R342.2 U12.C8 | length 35.9
  Top Layer w0.127: U12.C8@85.574,94.366 86.462,93.472 88.436,93.472 90.316,95.352 90.316,99.46 v5(90.678,99.822) 90.678,100.076 91.44,100.838 R107.2@91.752,100.838
  Signal Layer 2 w0.102: v5(90.678,99.822) 90.678,98.933 90.932,98.679 100.33,98.679 103.251,101.6 106.902,101.6 v1(108.966,103.664)
  Bottom Layer w0.127: v1(108.966,103.664) 109.188,103.886 R342.2@111.31,103.886
ADC_IN_N: C106.2 R250.1 R328.1 | length 36
  Bottom Layer w0.254: R328.1@48.26,109.67 47.879,110.051 47.879,116.332 49.403,117.856 49.403,141.224 49.849,141.67 C106.2@51.562,141.67 51.627,141.605 R250.1@52.89,141.605
ADC_IN_P: C103.1 R244.1 R329.1 | length 37.1
  Bottom Layer w0.254: R329.1@47.244,109.67 47.371,109.797 47.371,116.459 48.911,117.999 48.911,141.494 50.227,142.81 C103.1@51.562,142.81 51.627,142.875 R244.1@52.89,142.875
ADC_JP_IN_N: JP31.1 R138.1 | length 131.9
  Top Layer w0.254: v1(115.316,55.626) 120.65,60.96 134.112,60.96 138.622,65.47 R138.1@138.622,70.358
  Signal Layer 2 w0.254: v1(73.533,49.276) 73.787,49.022 108.712,49.022 v1(115.316,55.626)
  Bottom Layer w0.254: JP31.1@49.022,92.964 47.625,91.567 47.625,77.724 73.533,51.816 v1(73.533,49.276)
ADC_JP_IN_P: JP30.1 R141.1 | length 131.1
  Top Layer w0.254: v1(115.316,56.515) 120.269,61.468 133.858,61.468 137.414,65.024 R141.1@137.414,67.372
  Signal Layer 2 w0.254: v1(72.898,48.514) 73.025,48.387 108.966,48.387 115.951,55.372 115.951,55.88 v1(115.316,56.515)
  Bottom Layer w0.254: JP30.1@45.72,92.964 47.117,91.567 47.117,77.47 72.898,51.689 v1(72.898,48.514)
ADC_JP_OUT_N: JP31.2 R328.2 | length 13.8
  Bottom Layer w0.254: R328.2@48.26,108.77 48.006,108.516 48.006,96.52 JP31.2@49.022,95.504
ADC_JP_OUT_P: JP30.2 R329.2 | length 14.1
  Bottom Layer w0.254: JP30.2@45.72,95.504 47.498,97.282 47.498,108.516 R329.2@47.244,108.77
ADC_POT: R223.2 RV1.2 | length 154.6
  Signal Layer 2 w0.5: v1(28.321,72.009) 35.179,78.867 v1(35.179,84.201)
  Bottom Layer w0.5: RV1.2@14.535,7.51 14.535,28.378 15.494,29.337 15.494,49.403 21.209,55.118 21.209,64.897 v1(28.321,72.009) ; R223.2@28.08,144.894 28.194,144.78 28.194,143.9 27.686,143.392 27.686,138.886 21.336,132.536 21.336,128.397 23.114,126.619 23.114,109.786 28.194,104.706 28.194,99.441 35.179,92.456 v1(35.179,84.201)
AINA_codec: C168.2 C169.2 U48.23 | length 3.5
  Bottom Layer w0.3: C169.2@129.032,63.95 C168.2@130.048,63.95 130.048,64.135 131.338,65.425 U48.23@131.338,65.901
AINA_jack: CN20.6 R416.2 R417.1 U20.4 | length 33
  Top Layer w0.254: v4(130.302,59.436) 137.668,52.07 150.749,52.07 151.064,51.755 U20.4@151.064,50.68
  Top Layer w0.508: U20.4@151.064,50.68 155.539,50.68 155.8,50.419 CN20.6@155.8,50.08 155.631,49.911 CN20.6@155.631,50.249
  Bottom Layer w0.254: R417.1@129.032,60.51 R416.2@130.048,60.51 130.048,59.69 v4(130.302,59.436)
AINB_codec: C162.1 C170.2 U48.24 | length 4.3
  Bottom Layer w0.3: C170.2@128.016,63.95 128.212,64.146 C162.1@128.212,65.024 130.302,65.024 130.838,65.56 U48.24@130.838,65.901
AINB_jack: CN20.4 R418.1 R419.1 U20.3 | length 46.8
  Top Layer w0.254: v1(127.399,59.291) 135.89,50.8 145.034,50.8 148.59,47.244 150.876,47.244 151.064,47.432 U20.3@151.064,48.38
  Top Layer w0.508: U20.3@151.064,48.38 153.423,48.38 155.321,46.482 155.321,45.72 157.861,43.18 CN20.4@163.2,43.18
  Bottom Layer w0.254: v1(127.399,59.291) 127,59.69 R419.1@127,60.51 R418.1@128.016,60.51
AOUTA: C159.2 CN18.6 R141.2 U18.4 U48.11 | length 33.2
  Top Layer w0.254: R141.2@137.222,68.834 v4(136.525,68.834) 135.89,69.469 135.89,71.247 136.652,72.009 141.351,72.009 142.494,70.866 142.494,66.04 143.002,65.532 150.368,65.532 151.064,64.836 U18.4@151.064,63.634
  Top Layer w0.4: U18.4@151.064,63.634 155.116,63.634 CN18.6@155.805,62.945
  Bottom Layer w0.254: U48.11@135.013,69.076 136.283,69.076 v4(136.525,68.834) C159.2@137.222,68.834
AOUTB: C151.2 CN18.4 R138.2 U18.3 U48.10 | length 40.5
  Top Layer w0.254: R138.2@137.222,70.358 v4(136.525,70.358) 136.525,71.12 136.906,71.501 141.097,71.501 141.986,70.612 141.986,65.786 145.288,62.484 150.749,62.484 151.064,62.169 U18.3@151.064,61.334
  Top Layer w0.508: U18.3@151.064,61.334 152.661,61.334 157.95,56.045 CN18.4@163.205,56.045
  Bottom Layer w0.254: U48.10@135.013,69.576 135.743,69.576 v4(136.525,70.358) C151.2@137.222,70.358
BOOT0: JP22.2 R3.1 U5.C5 | length 165
  Top Layer w0.2: U5.C5@87.6,136.8 v2(88,137.2) ; v1(96.901,154.686) 101.854,149.733 v1(101.854,142.875)
  Top Layer w0.203: R3.1@24.45,166.9 28.3,166.9 30.9,164.3 30.9,163 33.782,160.118 33.782,157.099 v1(35.496,155.384) 41.3,149.581 41.3,112.5 37.268,108.468 JP22.2@34.545,108.468
  Signal Layer 2 w0.2: v2(88,137.2) 89.7,137.2 90.1,137.6 90.1,138.233 92.964,141.097 100.076,141.097 v1(101.854,142.875)
  Signal Layer 2 w0.203: v1(35.496,155.384) 35.687,155.575 56.007,155.575 57.023,154.559 96.774,154.559 v1(96.901,154.686)
Bootloader_BOOT0: D1.1 U9.20 | length 2.9
  Top Layer w0.381: U9.20@22.5,118.405 24.216,118.405 24.638,117.983 D1.1@24.638,117.402
BOOTLOADER_RST: JP24.2 U9.16 | length 6.8
  Top Layer w0.254: JP24.2@18.542,112.014 18.542,114.173 20.174,115.805 U9.16@22.5,115.805
CANH: CN22.7 R176.1 U27.2 U28.7 | length 17.6
  Top Layer w0.155: U28.7@149.733,21.171 149.733,21.717 150.209,22.193 R176.1@150.209,23.146 ; R176.1@149.86,23.172 150.183,23.172 R176.1@150.209,23.146 ; U27.2@155.4,22.525 156.95,22.525 157.4,22.075 CN22.7@160.775,22.075 ; U27.2@155.4,22.55 155.4,25.175 155.175,25.4 151.384,25.4 150.622,24.638 150.622,23.934 150.209,23.521 R176.1@150.209,23.146
CANL: CN22.2 JP38.2 U27.1 U28.6 | length 14.1
  Top Layer w0.155: U28.6@151.003,21.171 151.003,21.685 150.59,22.098 150.59,23.336 151.384,24.13 JP38.2@151.892,24.13 151.892,24.765 151.977,24.85 153.363,24.85 154.075,24.138 U27.1@154.075,22.25 ; U27.1@154.1,22.525 154.1,21.922 154.297,21.725 156.725,21.725 157.625,20.825 CN22.2@158.175,20.825
CTP_RST: R156.1 R281.1 | length 196.6
  Top Layer w0.127: v1(149.4,43.1) R156.1@149.4,44.075
  Signal Layer 2 w0.127: v1(68.55,41.8) 114.7,41.8 117.9,45 v1(120.575,45) ; v1(120.575,47.65) 126.925,47.65 130.825,51.55 v1(132.25,51.55)
  Bottom Layer w0.127: R281.1@43.492,131.445 41.148,131.445 40.767,131.064 40.767,101.346 39.878,100.457 39.878,79.375 63.119,56.134 63.119,55.88 69.088,49.911 69.088,43.038 68.55,42.5 v1(68.55,41.8) ; v1(120.575,45) v1(120.575,47.65) ; v1(132.25,51.55) 133.475,50.325 143.575,50.325 149.4,44.5 v1(149.4,43.1)
CTP_RST_CN: CN30.9 R155.2 R156.2 | length 5.7
  Top Layer w0.381: CN30.9@144.865,47.6 146.35,47.6 147.975,45.975 R155.2@147.975,45.475 R156.2@149.4,45.475
D0: R391.2 U12.E3 U16.R8 U17.B6 | length 97.7
  Top Layer w0.102: U17.B6@65.953,71.48 65.953,70.972 v3(66.328,70.597) ; 77.54,99.898 77.616,99.975 82.959,99.975 83.567,99.366 U12.E3@83.574,99.366 ; v3(83.097,71.063) U16.R8@83.497,71.463
  Top Layer w0.127: v9(76.524,89.865) 76.016,90.373 76.016,98.374 77.54,99.898
  Signal Layer 2 w0.102: v1(55.245,87.122) 56.261,86.106 64.008,86.106 64.516,85.598 66.802,85.598 66.929,85.471 66.929,85.09 67.056,84.963 67.31,84.963 67.437,85.09 67.437,85.471 67.564,85.598 67.818,85.598 67.945,85.471 67.945,85.09 68.072,84.963 68.326,84.963 68.453,85.09 68.453,85.598 68.58,85.725 68.834,85.725 68.961,85.598 68.961,85.09 69.088,84.963 69.342,84.963 69.469,85.09 69.469,85.598 69.596,85.725 69.85,85.725 69.977,85.598 69.977,85.09 70.104,84.963 70.358,84.963 70.485,85.09 70.485,85.598 70.612,85.725 70.866,85.725 70.993,85.598 70.993,85.09 71.12,84.963 71.374,84.963 71.501,85.09 71.501,85.598 71.628,85.725 71.882,85.725 72.009,85.598 72.009,85.09 72.136,84.963 72.39,84.963 72.517,85.09 72.517,85.598 72.644,85.725 72.898,85.725 73.025,85.598 73.025,85.09 73.152,84.963 73.406,84.963 73.533,85.09 73.533,85.598 73.66,85.725 73.914,85.725 74.041,85.598 74.041,85.09 74.168,84.963 74.422,84.963 74.549,85.09 74.549,85.725 74.676,85.852 74.93,85.852 75.057,85.725 75.057,85.09 75.184,84.963 75.438,84.963 75.565,85.09 75.565,85.725 75.692,85.852 75.946,85.852 76.073,85.725 76.073,85.09 76.2,84.963 76.454,84.963 76.581,85.09 76.581,89.808 v9(76.524,89.865) ; v3(66.328,70.597) 66.328,70.612 66.455,70.739 67.075,70.739 67.507,70.307 73.755,70.307 74.085,69.977 v3(74.365,69.977) 74.415,69.977 74.644,70.206 79.191,70.206 79.648,70.663 82.696,70.663 v3(83.097,71.063)
  Bottom Layer w0.127: v1(55.245,87.122) R391.2@56.192,87.122 ; v3(74.365,69.977) 74.04,69.977 73.412,70.605 73.412,86.754 v9(76.524,89.865)
D1: R127.2 U12.H3 U16.N7 U17.C5 | length 97.7
  Top Layer w0.102: U17.C5@65.203,72.23 v3(65.578,71.855) ; v3(84.697,71.863) U16.N7@85.097,72.263
  Top Layer w0.127: v1(64.897,87.376) 65.278,87.757 R127.2@65.278,88.704 ; v9(76.524,90.754) 76.524,95.631 77.159,96.266 77.159,97.866 78.659,99.366 U12.H3@80.574,99.366
  Signal Layer 2 w0.102: v1(64.897,87.376) 64.897,86.106 65.024,85.979 65.278,85.979 65.405,86.106 65.405,86.995 65.532,87.122 65.786,87.122 65.913,86.995 65.913,86.36 66.04,86.233 66.294,86.233 66.421,86.36 66.421,87.376 66.548,87.503 66.802,87.503 66.929,87.376 66.929,86.36 67.056,86.233 67.31,86.233 67.437,86.36 67.437,87.376 67.564,87.503 67.818,87.503 67.945,87.376 67.945,86.36 68.072,86.233 68.326,86.233 68.453,86.36 68.453,87.376 68.58,87.503 68.834,87.503 68.961,87.376 68.961,86.36 69.088,86.233 69.342,86.233 69.469,86.36 69.469,87.376 69.596,87.503 69.85,87.503 69.977,87.376 69.977,86.36 70.104,86.233 70.358,86.233 70.485,86.36 70.485,87.376 70.612,87.503 70.866,87.503 70.993,87.376 70.993,86.36 71.12,86.233 71.374,86.233 71.501,86.36 71.501,87.376 71.628,87.503 71.882,87.503 72.009,87.376 72.009,86.36 72.136,86.233 72.39,86.233 72.517,86.36 72.517,87.376 72.644,87.503 72.898,87.503 73.025,87.376 73.025,86.36 73.152,86.233 73.406,86.233 73.533,86.36 73.533,87.376 73.66,87.503 73.914,87.503 74.041,87.376 74.041,86.36 74.168,86.233 74.422,86.233 74.549,86.36 74.549,87.376 74.676,87.503 74.93,87.503 75.057,87.376 75.057,86.36 75.184,86.233 75.438,86.233 75.565,86.36 75.565,87.376 75.946,87.757 75.946,90.424 76.276,90.754 v9(76.524,90.754) ; v3(65.578,71.855) 65.703,71.855 65.83,71.728 65.83,71.501 65.957,71.374 66.135,71.374 66.262,71.501 66.262,71.728 66.389,71.855 67.33,71.855 67.735,71.45 67.735,70.917 67.862,70.79 68.142,70.79 68.269,70.917 68.269,71.209 68.396,71.336 68.65,71.336 68.777,71.209 68.777,70.815 68.904,70.688 69.507,70.688 69.659,70.841 69.913,70.841 70.066,70.688 70.32,70.688 70.472,70.841 70.726,70.841 70.878,70.688 71.132,70.688 71.285,70.841 71.539,70.841 71.691,70.688 71.945,70.688 72.098,70.841 72.352,70.841 72.504,70.688 72.758,70.688 72.91,70.841 73.164,70.841 73.317,70.688 v3(74.365,70.688) 74.542,70.51 79.038,70.51 79.495,70.968 82.391,70.968 82.884,71.461 84.294,71.461 v3(84.697,71.863)
  Bottom Layer w0.127: v3(74.365,70.688) 73.984,70.688 73.793,70.879 73.793,86.347 77.032,89.586 77.032,90.246 v9(76.524,90.754)
D2: R119.2 U12.E4 U16.R9 U17.C6 | length 97.7
  Top Layer w0.102: U17.C6@65.203,71.48 65.203,70.972 v3(65.578,70.597) ; v5(83.067,98.866) 83.567,98.366 U12.E4@83.574,98.366 ; v3(83.097,70.264) U16.R9@83.497,70.663 ; v1(101.219,93.726) R119.2@102.166,93.726
  Signal Layer 2 w0.102: v3(65.578,70.597) 66.249,69.926 73.044,69.926 73.425,69.545 v3(76.905,69.545) 79.597,69.545 79.699,69.647 79.699,70.137 79.818,70.257 79.986,70.257 80.105,70.137 80.105,69.647 80.207,69.545 80.41,69.545 80.511,69.647 80.511,70.087 80.631,70.206 80.799,70.206 80.918,70.087 80.918,69.647 81.019,69.545 81.223,69.545 81.324,69.647 81.324,70.079 81.426,70.18 81.629,70.18 81.731,70.079 81.731,69.647 81.832,69.545 82.035,69.545 82.137,69.647 82.137,70.079 82.239,70.18 82.442,70.18 82.543,70.079 82.543,69.672 82.67,69.545 82.97,69.545 83.097,69.672 v3(83.097,70.264) ; v5(83.067,98.866) 83.074,98.485 85.42,96.139 87.503,96.139 87.96,96.596 89.332,96.596 89.916,96.012 89.916,93.726 90.043,93.599 90.297,93.599 90.424,93.726 90.424,94.361 90.551,94.488 90.805,94.488 90.932,94.361 90.932,93.726 91.059,93.599 91.313,93.599 91.44,93.726 91.44,94.361 91.567,94.488 91.821,94.488 91.948,94.361 91.948,93.726 92.075,93.599 92.329,93.599 92.456,93.726 92.456,94.361 92.583,94.488 92.837,94.488 92.964,94.361 92.964,93.726 93.091,93.599 93.345,93.599 93.472,93.726 93.472,94.361 93.599,94.488 93.853,94.488 93.98,94.361 93.98,93.726 94.107,93.599 94.361,93.599 94.488,93.726 94.488,94.361 94.615,94.488 94.869,94.488 94.996,94.361 94.996,93.726 95.123,93.599 95.377,93.599 95.504,93.726 95.504,94.742 95.631,94.869 95.885,94.869 96.012,94.742 96.012,93.726 96.139,93.599 96.393,93.599 96.52,93.726 96.52,94.742 96.647,94.869 96.901,94.869 97.028,94.742 97.028,93.98 97.155,93.853 97.409,93.853 97.536,93.98 97.536,94.742 97.663,94.869 97.917,94.869 98.044,94.742 98.044,94.488 98.171,94.361 98.425,94.361 98.552,94.488 98.552,94.742 98.679,94.869 98.933,94.869 99.06,94.742 99.06,94.488 99.187,94.361 99.441,94.361 99.568,94.488 99.568,94.742 99.695,94.869 99.949,94.869 100.076,94.742 100.076,93.853 100.203,93.726 100.457,93.726 100.584,93.853 100.584,94.107 100.711,94.234 100.965,94.234 101.092,94.107 101.092,93.853 v1(101.219,93.726)
  Bottom Layer w0.127: v3(76.905,69.545) 76.905,70.942 75.762,72.085 75.762,75.101 77.032,76.371 77.032,83.769 83.128,89.865 83.128,94.768 83.627,95.267 83.627,95.918 84.017,96.308 84.017,97.866 83.067,98.816 v5(83.067,98.866)
D3: R373.2 U12.H4 U16.N8 U17.D5 | length 97.8
  Top Layer w0.102: U17.D5@64.453,72.23 v3(64.828,71.855) ; v3(84.697,71.063) U16.N8@85.097,71.463
  Top Layer w0.127: v5(78.302,96.342) 78.937,96.977 78.937,97.993 79.309,98.366 U12.H4@80.574,98.366
  Signal Layer 2 w0.102: v3(64.828,71.855) 65.221,71.462 65.221,70.409 66.338,69.291 66.7,69.291 66.801,69.393 66.801,69.495 66.903,69.596 67.106,69.596 67.208,69.495 67.208,69.393 67.309,69.291 67.512,69.291 67.614,69.393 67.614,69.495 67.716,69.596 67.919,69.596 68.02,69.495 68.02,69.393 68.122,69.291 68.325,69.291 68.427,69.393 68.427,69.495 68.528,69.596 68.732,69.596 68.833,69.495 68.833,69.393 68.935,69.291 69.138,69.291 69.24,69.393 69.24,69.495 69.341,69.596 69.544,69.596 69.646,69.495 69.646,69.393 69.748,69.291 69.951,69.291 70.052,69.393 70.052,69.495 70.154,69.596 70.357,69.596 70.459,69.495 70.459,69.393 70.56,69.291 70.764,69.291 70.865,69.393 70.865,69.495 70.967,69.596 71.17,69.596 71.272,69.495 71.272,69.393 71.373,69.291 71.576,69.291 71.678,69.393 71.678,69.495 71.78,69.596 71.983,69.596 72.084,69.495 72.084,69.393 72.186,69.291 v3(72.714,69.291) 72.968,69.037 77.032,69.037 77.235,69.241 83.102,69.241 83.509,69.647 83.509,70.434 83.763,70.688 84.144,70.688 84.518,71.063 v3(84.697,71.063) ; v5(78.302,96.342) 78.423,96.228 84.392,96.228 85.039,95.58 88.189,95.58 88.646,95.123 88.646,93.472 88.9,93.218 96.901,93.218 97.155,93.472 97.409,93.472 97.663,93.218 97.917,93.218 98.044,93.345 98.044,93.726 98.171,93.853 98.425,93.853 98.552,93.726 98.552,93.345 98.679,93.218 98.933,93.218 99.06,93.345 99.06,93.726 99.187,93.853 99.441,93.853 99.568,93.726 99.568,93.345 99.695,93.218 107.823,93.218 v1(107.95,93.345)
  Bottom Layer w0.127: v3(72.714,69.291) 72.714,76.568 72.498,76.784 72.498,77.769 72.015,78.251 72.015,88.202 77.768,93.955 77.768,95.809 v5(78.302,96.342) ; v1(107.95,93.345) R373.2@111.31,93.345
D4: R338.2 U12.H5 U16.P9 U17.E5 | length 97.8
  Top Layer w0.102: v3(63.328,71.855) U17.E5@63.703,72.23 ; v3(83.897,70.264) U16.P9@84.297,70.663
  Top Layer w0.127: v5(80.08,97.866) U12.H5@80.574,97.366
  Signal Layer 2 w0.102: v1(59.309,106.045) 59.563,105.791 60.071,105.791 60.198,105.918 60.198,106.68 60.325,106.807 60.579,106.807 60.706,106.68 60.706,105.918 60.833,105.791 61.087,105.791 61.214,105.918 61.214,107.442 61.341,107.569 61.595,107.569 61.722,107.442 61.722,105.918 61.849,105.791 62.103,105.791 62.23,105.918 62.23,107.442 62.357,107.569 62.611,107.569 62.738,107.442 62.738,105.918 62.865,105.791 63.5,105.791 63.881,105.41 64.516,105.41 65.024,104.902 66.548,104.902 67.056,105.41 67.564,105.41 67.945,105.791 68.199,105.791 68.58,105.41 68.961,105.41 69.342,105.791 70.739,105.791 71.501,105.029 71.501,104.013 76.353,99.161 78.842,99.161 78.994,99.009 78.994,97.587 79.096,97.485 79.705,97.485 v5(80.08,97.866) ; v3(63.328,71.855) 66.527,68.656 75.52,68.656 v3(75.571,68.606) ; v3(83.897,70.264) 83.897,69.603 83.229,68.936 80.672,68.936 80.57,68.834 80.57,68.479 80.468,68.377 80.265,68.377 80.164,68.479 80.164,68.834 80.062,68.936 79.859,68.936 79.757,68.834 79.757,68.479 79.656,68.377 79.452,68.377 79.351,68.479 79.351,68.834 79.249,68.936 79.046,68.936 78.944,68.834 78.944,68.479 78.843,68.377 78.64,68.377 78.538,68.479 78.538,68.834 78.436,68.936 78.233,68.936 78.132,68.834 78.132,68.479 78.03,68.377 77.827,68.377 77.725,68.479 77.725,68.834 77.624,68.936 77.362,68.936 77.082,68.656 v3@75.635,68.656 ; v3(75.571,68.606) 75.584,68.606 v3@75.635,68.656 ; v3(75.571,68.606) v3@75.635,68.656
  Bottom Layer w0.127: R338.2@57.088,106.045 v1(59.309,106.045) ; v3(75.571,68.606) 75.254,68.923 75.254,70.973 74.555,71.672 74.555,85.865 77.794,89.103 77.794,91.643 79.546,93.396 79.546,95.682 80.08,96.215 v5(80.08,97.866)
D5: R96.2 U12.E5 U16.M8 U17.F5 | length 97.3
  Top Layer w0.102: v3(62.578,71.855) U17.F5@62.953,72.23 ; R96.2@66.236,104.775 v1(67.31,104.775) ; v5(83.067,97.866) 83.567,97.366 U12.E5@83.574,97.366 ; v3(85.497,71.063) U16.M8@85.897,71.463
  Signal Layer 2 w0.102: v3(62.578,71.855) 62.183,71.461 62.183,70.957 65.373,67.767 v3(76.524,67.767) 81.223,67.767 81.324,67.869 81.324,68.199 81.426,68.301 81.629,68.301 81.731,68.199 81.731,67.869 81.832,67.767 82.035,67.767 82.137,67.869 82.137,68.199 82.239,68.301 82.442,68.301 82.543,68.199 82.543,67.869 82.645,67.767 82.848,67.767 82.95,67.869 82.95,68.199 83.051,68.301 83.255,68.301 83.356,68.199 83.356,67.869 83.458,67.767 83.774,67.767 83.875,67.869 83.875,68.707 84.002,68.834 85.185,68.834 85.312,68.961 85.312,69.139 85.185,69.266 84.702,69.266 84.575,69.393 84.575,69.52 84.702,69.647 85.014,69.647 85.141,69.774 85.141,70.543 85.497,70.899 v3(85.497,71.063) ; v1(67.31,104.775) 67.564,105.029 67.818,105.029 67.945,104.902 67.945,104.14 68.072,104.013 68.326,104.013 68.453,104.14 68.453,104.902 68.58,105.029 68.834,105.029 68.961,104.902 68.961,104.14 69.088,104.013 69.342,104.013 69.469,104.14 69.469,105.283 69.596,105.41 69.85,105.41 69.977,105.283 69.977,104.14 70.104,104.013 70.358,104.013 70.485,104.14 70.485,104.902 70.612,105.029 70.866,105.029 70.993,104.902 70.993,104.013 76.708,98.298 76.962,98.298 77.089,98.425 77.089,98.679 77.216,98.806 77.47,98.806 77.597,98.679 77.597,98.425 77.724,98.298 77.978,98.298 78.105,98.425 78.105,98.679 78.232,98.806 78.486,98.806 78.613,98.679 78.613,97.422 78.816,97.218 80.074,97.218 80.721,97.866 81.28,97.866 v5(83.067,97.866)
  Bottom Layer w0.127: v3(76.524,67.767) 76.524,69.037 76.143,69.418 76.143,71.165 75.381,71.927 75.381,75.259 76.651,76.529 76.651,84.023 82.747,90.119 82.747,93.831 82.62,93.958 82.62,96.038 83.001,96.419 83.194,96.419 83.474,96.698 83.474,97.46 v5(83.067,97.866)
D6: R87.2 U12.H6 U16.M7 U17.F6 | length 97.6
  Top Layer w0.102: v3(62.578,71.105) U17.F6@62.953,71.48 ; R87.2@66.236,106.045 v1(67.31,106.045) ; v3(85.497,71.863) U16.M7@85.897,72.263
  Top Layer w0.127: v5(79.469,97.891) 79.469,97.461 U12.H6@80.574,96.366
  Signal Layer 2 w0.102: v3(62.578,71.105) 65.475,68.199 v3(74.873,68.199) 75,68.072 75.812,68.072 76.016,68.275 76.727,68.275 76.93,68.072 80.791,68.072 80.918,68.199 80.918,68.479 81.045,68.606 83.331,68.606 84.271,69.545 84.271,70.34 84.549,70.619 84.755,70.619 85.052,70.916 85.052,71.419 v3(85.497,71.863) ; v1(67.31,106.045) 66.167,106.045 66.04,106.172 66.04,106.426 66.167,106.553 66.802,106.553 66.929,106.68 66.929,106.934 66.802,107.061 66.294,107.061 66.167,107.188 66.167,107.442 66.294,107.569 67.818,107.569 67.945,107.442 67.945,106.299 68.072,106.172 68.326,106.172 68.453,106.299 68.453,107.442 68.58,107.569 68.834,107.569 68.961,107.442 68.961,106.299 69.088,106.172 69.342,106.172 69.469,106.299 69.469,107.442 69.596,107.569 69.85,107.569 69.977,107.442 69.977,106.299 70.104,106.172 70.358,106.172 70.485,106.299 70.485,107.442 70.612,107.569 70.866,107.569 70.993,107.442 70.993,106.172 71.12,106.045 71.374,106.045 71.501,106.172 71.501,107.442 71.628,107.569 71.882,107.569 72.009,107.442 72.009,104.064 76.581,99.492 79.349,99.492 79.469,99.371 v5(79.469,97.891)
  Bottom Layer w0.127: v3(74.873,68.199) 74.873,70.815 74.174,71.514 74.174,86.119 77.413,89.357 77.413,91.897 79.216,93.701 79.216,96.089 79.469,96.342 v5(79.469,97.891)
D7: R341.2 U12.E6 U16.L8 U17.G6 | length 97.9
  Top Layer w0.102: v3(61.828,71.105) U17.G6@62.203,71.48 ; v5(83.067,96.866) 83.567,96.366 U12.E6@83.574,96.366 ; v3(86.297,71.063) U16.L8@86.697,71.463
  Signal Layer 2 w0.102: v1(59.309,104.775) 59.944,104.14 67.437,104.14 67.945,103.632 70.866,103.632 76.581,97.917 78.105,97.917 78.232,97.79 78.232,97.434 78.816,96.85 80.467,96.85 80.594,96.977 80.594,97.358 80.721,97.485 80.975,97.485 81.102,97.358 81.102,96.977 81.229,96.85 81.483,96.85 81.61,96.977 81.61,97.231 81.737,97.358 83.769,97.358 83.896,97.231 83.896,96.993 83.769,96.866 v5(83.067,96.866) ; v3(61.828,71.105) 61.828,70.881 65.373,67.336 v3(75.508,67.336) 75.533,67.31 84.118,67.31 84.6,67.792 84.6,67.935 84.299,68.236 84.299,68.405 84.418,68.524 84.586,68.524 84.887,68.223 85.031,68.223 85.922,69.114 85.922,70.688 v3(86.297,71.063)
  Bottom Layer w0.127: R341.2@57.088,104.775 v1(59.309,104.775) ; v3(75.508,67.336) 76.016,67.844 76.016,68.91 75.635,69.291 75.635,71.131 74.936,71.83 74.936,75.354 76.27,76.687 76.27,84.277 80.715,88.722 80.715,93.548 82.239,95.072 82.239,96.044 83.001,96.806 83.007,96.806 v5(83.067,96.866)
